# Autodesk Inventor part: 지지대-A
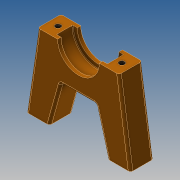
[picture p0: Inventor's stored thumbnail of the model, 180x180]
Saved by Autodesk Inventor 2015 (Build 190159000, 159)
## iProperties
Created: 2018-01
Part Number: 지지대-A
Material: 알루미늄 6061
Document SubType Name: Modeling
Designer: mduedu
Density: 2.71 g/cm^3
Appearance: 주황색
Mass: 21.9456 g
Surface Area: 38.5771 cm^2
Volume: 8.09801 cm^3
Author: mduedu
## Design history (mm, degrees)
sketch "스케치1"
  geometry: L1 (-22.5, 0)-(22.5, 0); L2 (22.5, 0)-(17.5, 34); L3 (17.5, 34)-(-17.5, 34); L4 (-17.5, 34)-(-22.5, 0); 3 further points
  constraints: 8 end point, 2 midpoint, 1 coincident, 1 horizontal, 1 parallel, 1 vertical alignment
  dimensions: "d0" = 45 distance of L1.start L1.end; "d3" = 35 distance of L2.end L3.end; "d4" = 34 vertical distance of L1.end L2.end
extrude "돌출1" new body sketch "스케치1" stored distance "d5" = 10; taper "d6" = 0 deg
sketch "스케치2"
  geometry: L1 (-12.5, 0)-(12.5, 0); L2 (12.5, 0)-(7.5, 18); L3 (7.5, 18)-(-7.5, 18); L4 (-7.5, 18)-(-12.5, 0); L5 (-22.5, 0)-(22.5, 0) reference; 4 further points
  constraints: 8 end point, 4 midpoint, 1 horizontal, 1 parallel, 1 vertical alignment
  dimensions: "d7" = 10 distance of L1.start L5.start; "d8" = 10 distance of L1.end L5.end (derived); "d9" = 15 distance of L2.end L3.end; "d10" = 18 distance between parallel lines of L1 L3
extrude "돌출2" cut sketch "스케치2" stored distance "d11" = 10; taper "d12" = 0 deg
sketch "스케치3"
  geometry: L1 (-17.5, 34)-(17.5, 34) reference; C1 r 11 at (0, 34); C2 r 9 at (0, 34); 1 further point
  constraints: 2 centre point, 1 coincident, 1 midpoint
  dimensions: "d13" = 22 diameter of C1; "d16" = 18 diameter of C2
extrude "돌출3" cut sketch "스케치3" stored distance "d14" = 7; taper "d15" = 0 deg
extrude "돌출4" cut sketch "스케치3" stored distance "d17" = 7; taper "d18" = 0 deg
fillet "모깎기1" dims "d19" = 0.3
fillet "모깎기2" dims "d20" = 1
fillet "모깎기3" dims "d21" = 1
fillet "모깎기4" dims "d22" = 1
sketch "스케치4"
  geometry: 2 further points
  constraints: 2 other
hole "구멍1" sketch "스케치4" at (-22.771, -3.5), (4.771, -3.5) diameter "d23" = 2.459; stored, may be unused: countersink angle "d27" = 90 deg, drill point angle "d29" = 120 deg; dims "d24" = 4.5, "d25" = 4, "d26" = 2, "d28" = 6
sketch "스케치5"
  geometry: 4 further points
  constraints: 4 other
hole "구멍2" sketch "스케치5" at (40, 4), (5, -27), (40, -27), (5, 4) diameter "d30" = 2.459; stored, may be unused: countersink angle "d34" = 90 deg, drill point angle "d36" = 120 deg; dims "d31" = 6.9, "d32" = 4, "d33" = 2, "d35" = 8.4
node "솔리드1"
